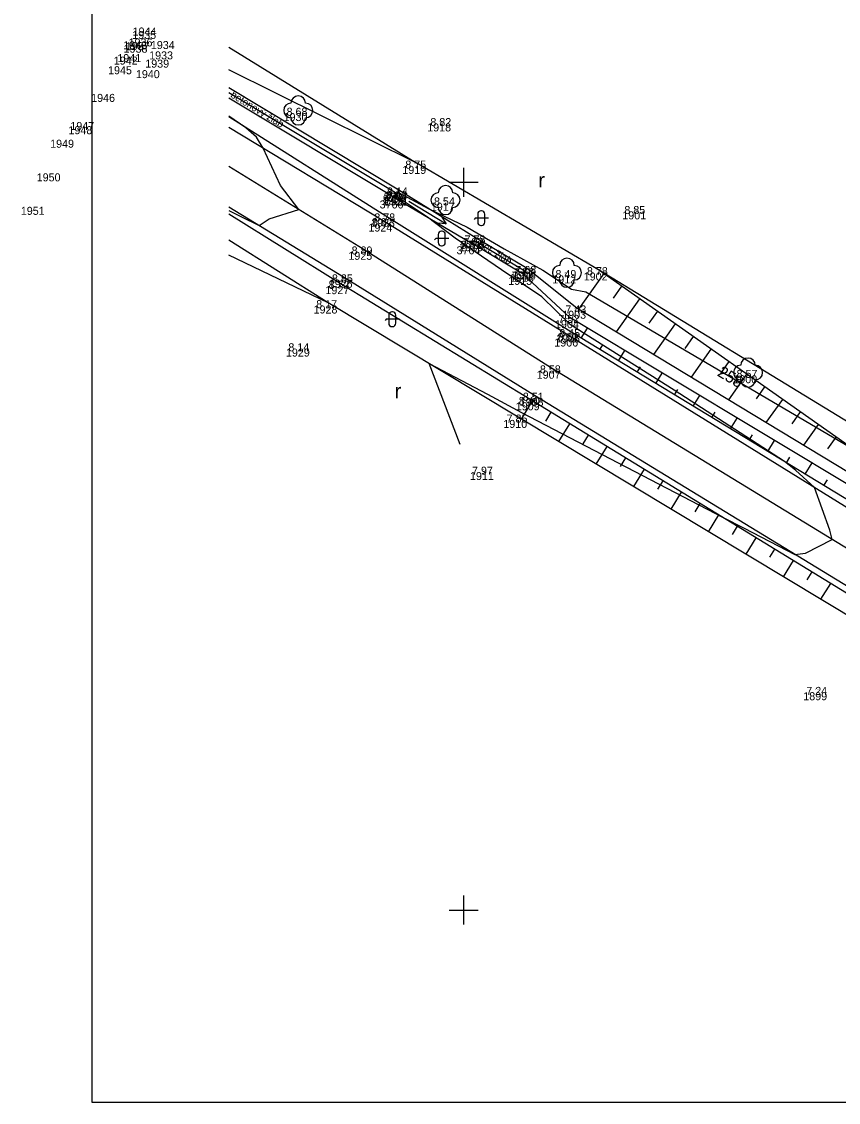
# Model space of a CAD drawing. Extents: x -740053 to -737517, y -1033516 to -1032465.
# Drawn here: x -738280.3 to -738224.3, y -1032613.2 to -1032539 of the extents above; entities that cross this region are included whole.
import ezdxf

# ---------------------------------------------------------------- set-up
doc = ezdxf.new("R2010")
doc.units = 0
for name, color, linetype in [('bod-cislo', 7, 'Continuous'), ('bod-oznac', 7, 'Continuous'), ('bod-vyska', 7, 'Continuous'), ('bod-vyska100', 7, 'Continuous'), ('Contours', 7, 'Continuous'), ('Contours text', 7, 'Continuous'), ('ctv-sit', 7, 'Continuous'), ('dopl-znacky', 7, 'Continuous'), ('nazvy-bud-povr', 7, 'Continuous'), ('osa-komunikace', 7, 'Continuous'), ('Predmety bez rozlišeni', 7, 'Continuous'), ('rozhraní kultůr', 7, 'Continuous'), ('silnice', 7, 'Continuous'), ('Technické šrafy', 7, 'Continuous'), ('Terenni-hrana', 7, 'Continuous'), ('Zlab', 7, 'Continuous'), ('zlab osa', 7, 'Continuous'), ('Znacky-kultury', 7, 'Continuous')]:
    doc.layers.add(name, color=color, linetype=linetype)

# ---------------------------------------------------------------- blocks, each defined once
blk = doc.blocks.new('POINT_DISPLAY')
blk.add_line((0, 0), (0, 0))
blk = doc.blocks.new('p_strom')
for centre, start, end in [((0, 1), 0, 180), ((-1, 0), 90, 270), ((1, 0), 270, 90), ((0, -1), 180, 0)]:
    blk.add_arc(centre, 1, start, end)
at = {"rotation": -180}
blk.add_blockref('POINT_DISPLAY', (0, 0), dxfattribs=at)
blk = doc.blocks.new('vo_votok')
for p, q in [((-3, 0), (3, 0)), ((2, 0.5), (3, 0)), ((3, 0), (2, -0.5))]:
    blk.add_line(p, q)
blk = doc.blocks.new('p_orna')
blk.add_text('r', height=2).set_placement((0, 0))
blk = doc.blocks.new('p_neplod')
for p, q in [((-0.82, 0), (-0.99, -0.18)), ((1, 0), (-0.82, 0)), ((-0.49, 0.56), (-0.49, -0.55)), ((0.05, 1.01), (-0.04, 1.01)), ((0.5, -0.55), (0.5, 0.56)), ((-0.04, -1), (0.05, -1))]:
    blk.add_line(p, q)
for centre, start, end in [((-0.04, 0.56), 90, 180), ((0.05, 0.56), 0, 90), ((-0.04, -0.55), 180, 270), ((0.05, -0.55), 270, 0)]:
    blk.add_arc(centre, 0.45, start, end)
blk = doc.blocks.new('ctvsit')
for p, q in [((0, -2), (0, 2)), ((2, 0), (-2, 0))]:
    blk.add_line(p, q)

msp = doc.modelspace()

# ---------------------------------------------------------------- linework, layer by layer
at = {"layer": 'Contours'}
for points in [[(-738266.126, -1032551.935), (-738265.304, -1032552.346), (-738264.035, -1032552.975), (-738263.347, -1032552.519), (-738261.315, -1032551.878), (-738262.572, -1032550.207), (-738263.767, -1032547.661), (-738264.226, -1032546.901), (-738264.943, -1032546.249), (-738266.126, -1032545.459)], [(-738250.229, -1032568.004), (-738252.368, -1032562.456), (-738248.367, -1032564.556), (-738246.031, -1032565.81), (-738232.186, -1032573.039), (-738230.734, -1032573.757), (-738227.267, -1032575.566), (-738226.522, -1032575.488), (-738224.697, -1032574.534), (-738224.844, -1032573.891), (-738225.899, -1032570.978), (-738227.219, -1032569.767), (-738227.975, -1032569.184), (-738235.532, -1032564.271), (-738242.669, -1032559.796), (-738244.635, -1032557.862), (-738247.407, -1032556.009), (-738250.58, -1032553.84), (-738252.47, -1032552.397), (-738254.616, -1032550.967), (-738254.549, -1032550.818), (-738254.465, -1032550.688), (-738252.375, -1032551.818), (-738249.748, -1032553.074), (-738247.206, -1032554.567), (-738244.558, -1032556.041), (-738242.586, -1032557.333), (-738241.595, -1032557.53), (-738223.493, -1032568.169)]]:
    msp.add_lwpolyline(points, dxfattribs=at)
at = {"layer": 'osa-komunikace'}
for p, q in [((-738256.9, -1032554.59), (-738266.126, -1032548.922)), ((-738243.97, -1032562.76), (-738256.9, -1032554.59)), ((-738220.71, -1032576.97), (-738243.97, -1032562.76))]:
    msp.add_line(p, q, dxfattribs=at)
at = {"layer": 'Predmety bez rozlišeni'}
for p, q in [((-738275.499, -1032613.213), (-738275.499, -1032464.713)), ((-738275.499, -1032613.213), (-738275.499, -1032464.713)), ((-738170.499, -1032613.213), (-738275.499, -1032613.213))]:
    msp.add_line(p, q, dxfattribs=at)
at = {"layer": 'rozhraní kultůr'}
for p, q in [((-738266.126, -1032540.708), (-738253.21, -1032548.69)), ((-738259.29, -1032558.28), (-738266.126, -1032555.015)), ((-738216, -1032571.12), (-738240.74, -1032556.01))]:
    msp.add_line(p, q, dxfattribs=at)
at = {"layer": 'silnice'}
for p, q in [((-738255.51, -1032552.65), (-738266.126, -1032546.235)), ((-738258.25, -1032556.51), (-738266.126, -1032551.697)), ((-738242.76, -1032560.55), (-738255.51, -1032552.65)), ((-738245.14, -1032564.64), (-738258.25, -1032556.51)), ((-738219.09, -1032575.19), (-738242.76, -1032560.55)), ((-738222.01, -1032578.78), (-738245.14, -1032564.64))]:
    msp.add_line(p, q, dxfattribs=at)
at = {"layer": 'Technické šrafy'}
for p, q in [((-738240.373, -1032556.268), (-738242.098, -1032558.714)), ((-738239.147, -1032557.133), (-738239.724, -1032557.95)), ((-738237.921, -1032557.997), (-738239.526, -1032560.273)), ((-738236.695, -1032558.861), (-738237.272, -1032559.679)), ((-738241.922, -1032560.706), (-738241.5, -1032560.011)), ((-738235.47, -1032559.726), (-738236.955, -1032561.833)), ((-738234.244, -1032560.59), (-738234.82, -1032561.407)), ((-738240.641, -1032561.485), (-738240.427, -1032561.135)), ((-738239.359, -1032562.264), (-738238.929, -1032561.557)), ((-738233.018, -1032561.454), (-738234.384, -1032563.392)), ((-738231.792, -1032562.318), (-738232.368, -1032563.136)), ((-738238.077, -1032563.044), (-738237.86, -1032562.686)), ((-738236.795, -1032563.823), (-738236.357, -1032563.102)), ((-738230.566, -1032563.183), (-738231.812, -1032564.951)), ((-738235.513, -1032564.602), (-738235.292, -1032564.238)), ((-738229.34, -1032564.047), (-738229.916, -1032564.864)), ((-738245.282, -1032565.014), (-738246.05, -1032566.267)), ((-738234.232, -1032565.381), (-738233.786, -1032564.647)), ((-738228.114, -1032564.911), (-738229.241, -1032566.51)), ((-738244.003, -1032565.798), (-738244.384, -1032566.419)), ((-738232.95, -1032566.16), (-738232.725, -1032565.79)), ((-738226.888, -1032565.776), (-738227.464, -1032566.593)), ((-738242.724, -1032566.582), (-738243.479, -1032567.814)), ((-738231.668, -1032566.939), (-738231.214, -1032566.193)), ((-738225.662, -1032566.64), (-738226.669, -1032568.069)), ((-738241.445, -1032567.365), (-738241.82, -1032567.976)), ((-738230.386, -1032567.718), (-738230.157, -1032567.342)), ((-738224.436, -1032567.504), (-738225.012, -1032568.322)), ((-738240.166, -1032568.149), (-738240.909, -1032569.361)), ((-738229.104, -1032568.497), (-738228.643, -1032567.738)), ((-738238.887, -1032568.933), (-738239.256, -1032569.534)), ((-738227.823, -1032569.276), (-738227.59, -1032568.893)), ((-738237.608, -1032569.716), (-738238.339, -1032570.909)), ((-738226.541, -1032570.055), (-738226.071, -1032569.283)), ((-738236.329, -1032570.5), (-738236.692, -1032571.091)), ((-738225.259, -1032570.835), (-738225.022, -1032570.445)), ((-738235.05, -1032571.284), (-738235.769, -1032572.456)), ((-738233.771, -1032572.067), (-738234.127, -1032572.648)), ((-738232.492, -1032572.851), (-738233.198, -1032574.003)), ((-738231.213, -1032573.634), (-738231.563, -1032574.206)), ((-738229.934, -1032574.418), (-738230.628, -1032575.551)), ((-738228.655, -1032575.202), (-738228.999, -1032575.763)), ((-738227.376, -1032575.985), (-738228.058, -1032577.098)), ((-738226.097, -1032576.769), (-738226.435, -1032577.32)), ((-738224.818, -1032577.553), (-738225.488, -1032578.646))]:
    msp.add_line(p, q, dxfattribs=at)
at = {"layer": 'Terenni-hrana'}
for p, q in [((-738253.21, -1032548.69), (-738266.126, -1032542.262)), ((-738255.34, -1032552.32), (-738266.126, -1032545.501)), ((-738240.74, -1032556.01), (-738253.21, -1032548.69)), ((-738254.718, -1032551.061), (-738249.42, -1032554.21)), ((-738249.14, -1032553.83), (-738254.434, -1032550.538)), ((-738258.48, -1032556.95), (-738266.126, -1032552.186)), ((-738242.64, -1032560.27), (-738255.34, -1032552.32)), ((-738259.29, -1032558.28), (-738266.126, -1032553.978)), ((-738242.7, -1032559.29), (-738245.92, -1032556.31)), ((-738242.22, -1032558.64), (-738245.64, -1032555.93)), ((-738217.08, -1032572.69), (-738240.74, -1032556.01)), ((-738245.42, -1032564.93), (-738258.48, -1032556.95)), ((-738246.26, -1032566.14), (-738259.29, -1032558.28)), ((-738217.68, -1032573.52), (-738242.22, -1032558.64)), ((-738217.84, -1032574.23), (-738242.7, -1032559.29)), ((-738218.85, -1032574.73), (-738242.64, -1032560.27)), ((-738222.26, -1032579.12), (-738245.42, -1032564.93)), ((-738222.64, -1032580.36), (-738246.26, -1032566.14))]:
    msp.add_line(p, q, dxfattribs=at)
at = {"layer": 'Zlab'}
for p, q in [((-738254.434, -1032550.538), (-738266.126, -1032543.501)), ((-738254.718, -1032551.061), (-738266.126, -1032544.226)), ((-738254.718, -1032551.061), (-738254.57, -1032550.8)), ((-738254.57, -1032550.8), (-738254.434, -1032550.538)), ((-738249.42, -1032554.21), (-738249.3, -1032554)), ((-738245.92, -1032556.31), (-738249.42, -1032554.21)), ((-738249.3, -1032554), (-738249.14, -1032553.83)), ((-738245.64, -1032555.93), (-738249.14, -1032553.83)), ((-738245.8, -1032556.1), (-738245.92, -1032556.31)), ((-738245.64, -1032555.93), (-738245.8, -1032556.1))]:
    msp.add_line(p, q, dxfattribs=at)
at = {"layer": 'zlab osa'}
for p, q in [((-738254.57, -1032550.8), (-738266.126, -1032543.842)), ((-738245.8, -1032556.1), (-738249.3, -1032554))]:
    msp.add_line(p, q, dxfattribs=at)

# ---------------------------------------------------------------- block references
at = {"layer": 'bod-oznac'}
for p in [(-738261.35, -1032545.06), (-738251.49, -1032545.77), (-738253.21, -1032548.69), (-738254.718, -1032551.061), (-738254.57, -1032550.8), (-738254.5, -1032550.86), (-738254.434, -1032550.538), (-738251.24, -1032551.22), (-738238.17, -1032551.81), (-738255.51, -1032552.65), (-738255.34, -1032552.32), (-738249.42, -1032554.21), (-738249.3, -1032554), (-738249.14, -1032553.83), (-738256.9, -1032554.59), (-738245.92, -1032556.31), (-738245.8, -1032556.1), (-738245.64, -1032555.93), (-738242.9, -1032556.21), (-738240.74, -1032556.01), (-738258.48, -1032556.95), (-738258.25, -1032556.51), (-738259.29, -1032558.28), (-738242.22, -1032558.64), (-738242.7, -1032559.29), (-738242.76, -1032560.55), (-738242.64, -1032560.27), (-738261.2, -1032561.24), (-738243.97, -1032562.76), (-738230.47, -1032563.07), (-738245.14, -1032564.64), (-738245.42, -1032564.93), (-738246.26, -1032566.14), (-738248.63, -1032569.72), (-738225.68, -1032584.85)]:
    msp.add_blockref('POINT_DISPLAY', p, dxfattribs=at)
at = {"layer": 'ctv-sit', "xscale": 0.5, "yscale": 0.5, "rotation": 180}
for p in [(-738250, -1032550), (-738250, -1032600)]:
    msp.add_blockref('ctvsit', p, dxfattribs=at)
at = {"layer": 'dopl-znacky', "xscale": 0.5000000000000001, "yscale": 0.4999999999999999, "rotation": -31.3018674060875}
msp.add_blockref('vo_votok', (-738252.487, -1032552.078), dxfattribs=at)
at = {"layer": 'Znacky-kultury', "xscale": 0.5, "yscale": 0.5}
for name, p in [('p_strom', (-738261.35, -1032545.06)), ('p_orna', (-738244.865, -1032550.345)), ('p_strom', (-738251.24, -1032551.22)), ('p_neplod', (-738248.786, -1032552.472)), ('p_neplod', (-738251.505, -1032553.865)), ('p_strom', (-738242.9, -1032556.21)), ('p_neplod', (-738254.897, -1032559.412)), ('p_strom', (-738230.47, -1032563.07)), ('p_orna', (-738254.73, -1032564.83))]:
    msp.add_blockref(name, p, dxfattribs=at)

# ---------------------------------------------------------------- texts
at = {"layer": 'bod-cislo'}
for s, p in [('1944', (-738272.721, -1032539.913)), ('1936', (-738272.998, -1032540.663)), ('1935', (-738272.748, -1032540.153)), ('1943', (-738273.368, -1032540.863)), ('1938', (-738273.338, -1032541.093)), ('1937', (-738273.198, -1032540.923)), ('1934', (-738271.471, -1032540.843)), ('1942', (-738274.018, -1032541.913)), ('1941', (-738273.77, -1032541.743)), ('1939', (-738271.855, -1032542.123)), ('1933', (-738271.588, -1032541.553)), ('1945', (-738274.408, -1032542.573)), ('1940', (-738272.498, -1032542.843)), ('1946', (-738275.568, -1032544.473)), ('1930', (-738262.358, -1032545.793)), ('1947', (-738276.998, -1032546.403)), ('1918', (-738252.498, -1032546.503)), ('1948', (-738277.128, -1032546.693)), ('1949', (-738278.385, -1032547.623)), ('1919', (-738254.205, -1032549.423)), ('1950', (-738279.308, -1032549.933)), ('3766', (-738255.766, -1032551.794)), ('1922', (-738255.578, -1032551.533)), ('3767', (-738255.482, -1032551.271)), ('1921', (-738255.43, -1032551.593)), ('1951', (-738280.4, -1032552.233)), ('1917', (-738252.248, -1032551.953)), ('1901', (-738239.1, -1032552.543)), ('1923', (-738256.348, -1032553.053)), ('1924', (-738256.531, -1032553.383)), ('1916', (-738250.308, -1032554.733)), ('3765', (-738250.188, -1032554.563)), ('1925', (-738257.908, -1032555.323)), ('3764', (-738250.481, -1032554.943)), ('1913', (-738246.808, -1032556.833)), ('1914', (-738246.661, -1032556.663)), ('1912', (-738243.908, -1032556.943)), ('1902', (-738241.748, -1032556.743)), ('1927', (-738259.488, -1032557.683)), ('1926', (-738259.258, -1032557.243)), ('1915', (-738246.928, -1032557.043)), ('1928', (-738260.298, -1032559.013)), ('1903', (-738243.228, -1032559.373)), ('1904', (-738243.721, -1032560.023)), ('1906', (-738243.768, -1032561.283)), ('1905', (-738243.648, -1032561.003)), ('1929', (-738262.195, -1032561.973)), ('1907', (-738244.978, -1032563.493)), ('1900', (-738231.478, -1032563.803)), ('1909', (-738246.415, -1032565.663)), ('1908', (-738246.148, -1032565.373)), ('1910', (-738247.268, -1032566.873)), ('1911', (-738249.56, -1032570.453)), ('1899', (-738226.675, -1032585.583))]:
    msp.add_text(s, height=0.55, dxfattribs=at).set_placement(p)
at = {"layer": 'bod-vyska'}
for s, p in [('8 68', (-738262.152, -1032545.427)), ('8 82', (-738252.279, -1032546.137)), ('8 75', (-738253.999, -1032549.057)), ('8 14', (-738255.262, -1032550.905)), ('8 14', (-738255.546, -1032551.428)), ('8 07', (-738255.359, -1032551.167)), ('7 84', (-738255.289, -1032551.227)), ('8 54', (-738252.029, -1032551.587)), ('8 85', (-738238.959, -1032552.177)), ('8 82', (-738256.299, -1032553.017)), ('8 78', (-738256.129, -1032552.687)), ('7 81', (-738250.209, -1032554.577)), ('7 67', (-738250.102, -1032554.367)), ('7 78', (-738249.929, -1032554.197)), ('8 89', (-738257.689, -1032554.957)), ('8 85', (-738259.039, -1032556.877)), ('7 71', (-738246.709, -1032556.677)), ('7 57', (-738246.589, -1032556.467)), ('7 68', (-738246.442, -1032556.297)), ('8 49', (-738243.689, -1032556.577)), ('8 78', (-738241.529, -1032556.377)), ('8 72', (-738259.269, -1032557.317)), ('8 17', (-738260.118, -1032558.647)), ('7 43', (-738243.009, -1032559.007)), ('7 52', (-738243.489, -1032559.657)), ('8 45', (-738243.429, -1032560.637)), ('8 52', (-738243.549, -1032560.917)), ('8 14', (-738262.028, -1032561.607)), ('8 58', (-738244.759, -1032563.127)), ('8 57', (-738231.259, -1032563.437)), ('8 51', (-738245.929, -1032565.007)), ('8 40', (-738246.209, -1032565.297)), ('7 85', (-738247.049, -1032566.507)), ('7 97', (-738249.419, -1032570.087)), ('7 24', (-738226.469, -1032585.217))]:
    msp.add_text(s, height=0.55, dxfattribs=at).set_placement(p)
at = {"layer": 'bod-vyska100'}
for s, p in [('258 68', (-738261.518, -1032545.093)), ('258 82', (-738251.657, -1032545.803)), ('258 75', (-738253.377, -1032548.723)), ('258 14', (-738254.605, -1032550.572)), ('258 14', (-738254.889, -1032551.095)), ('258 07', (-738254.737, -1032550.833)), ('257 84', (-738254.667, -1032550.893)), ('258 54', (-738251.407, -1032551.253)), ('258 85', (-738238.337, -1032551.843)), ('258 82', (-738255.677, -1032552.683)), ('258 78', (-738255.507, -1032552.353)), ('257 81', (-738249.587, -1032554.243)), ('257 67', (-738249.468, -1032554.033)), ('257 78', (-738249.307, -1032553.863)), ('258 89', (-738257.067, -1032554.623)), ('257 71', (-738246.087, -1032556.343)), ('257 57', (-738245.967, -1032556.133)), ('257 68', (-738245.808, -1032555.963)), ('258 49', (-738243.067, -1032556.243)), ('258 78', (-738240.907, -1032556.043)), ('258 72', (-738258.647, -1032556.983)), ('258 85', (-738258.417, -1032556.543)), ('258 17', (-738259.461, -1032558.313)), ('257 43', (-738242.387, -1032558.673)), ('257 52', (-738242.867, -1032559.323)), ('258 52', (-738242.927, -1032560.583)), ('258 45', (-738242.807, -1032560.303)), ('258 14', (-738261.371, -1032561.273)), ('258 58', (-738244.137, -1032562.793)), ('258 57', (-738230.637, -1032563.103)), ('258 51', (-738245.307, -1032564.673)), ('258 40', (-738245.587, -1032564.963)), ('257 85', (-738246.427, -1032566.173)), ('257 97', (-738248.797, -1032569.753)), ('257 24', (-738225.847, -1032584.883))]:
    msp.add_text(s, height=0.05, dxfattribs=at).set_placement(p)
at = {"layer": 'Contours text'}
msp.add_text('258', height=0.8, rotation=329.55535, dxfattribs=at).set_placement((-738232.636, -1032563.259))
at = {"layer": 'nazvy-bud-povr'}
for s, p in [('betonový žlab', (-738266.044, -1032544.119)), ('bet. žlab', (-738249.021, -1032554.359))]:
    msp.add_text(s, height=0.5, rotation=328.48628, dxfattribs=at).set_placement(p)

doc.saveas('drawing.dxf')
